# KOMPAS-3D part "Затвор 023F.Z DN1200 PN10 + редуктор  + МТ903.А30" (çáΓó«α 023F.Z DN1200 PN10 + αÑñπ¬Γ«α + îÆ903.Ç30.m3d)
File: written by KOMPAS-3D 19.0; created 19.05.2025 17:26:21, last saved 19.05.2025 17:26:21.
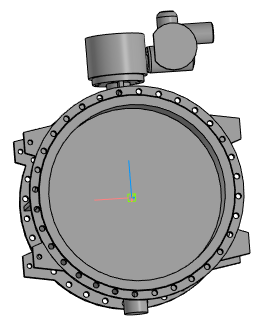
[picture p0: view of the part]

Document properties: Полное имя файла: Затвор 023F.Z DN1200 PN10 + редуктор + МТ903.А30.a3d

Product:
- Part/product: Затвор 023F.Z DN1200 PN10 + редуктор  + МТ903.А30
    Масса: 2220.76

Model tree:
1. Операция без истории:1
